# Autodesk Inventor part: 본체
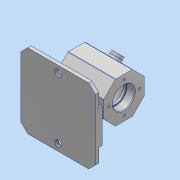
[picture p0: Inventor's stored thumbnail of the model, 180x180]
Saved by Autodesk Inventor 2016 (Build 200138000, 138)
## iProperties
Created: 2018-06
Part Number: 본체
Material: 알루미늄 6061
Document SubType Name: Modeling
Designer: 602-10
Density: 2.7 g/cm^3
Appearance: 알루미늄 - 평지
Author: 602-10
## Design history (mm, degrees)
sketch "스케치1"
  geometry: L1 (55, -55)-(-55, -55); L2 (-55, -55)-(-55, 55); L3 (-55, 55)-(55, 55); L4 (55, 55)-(55, -55); L5 (55, -55)-(-55, 55); L6 (-55, -55)-(55, 55); 1 further point
  constraints: 12 end point, 2 midpoint, 2 parallel, 1 horizontal, 1 perpendicular
  dimensions: "d0" = 110 distance of L1.end L2.end; "d1" = 110 distance of L1.start L1.end
extrude "돌출1" new body sketch "스케치1" distance "d2" = 5; taper "d3" = 0 deg
chamfer "모따기1" distance "d4" = 10; stored, may be unused: second distance "d5" = 2, angle "d6" = 45 deg
sketch "스케치3"
  geometry: L1 (55, -45)-(55, 45) reference; L2 (-55, 25)-(55, 25); L3 (55, 25)-(55, -25); L4 (55, -25)-(-55, -25); L5 (-55, -25)-(-55, 25); L6 (-55, 25)-(55, -25); L7 (55, 25)-(-55, -25); L8 (45, 55)-(-45, 55) reference; 1 further point
  constraints: 12 end point, 2 midpoint, 2 parallel, 1 horizontal, 1 perpendicular, 1 point on line
  dimensions: "d11" = 30 distance between parallel lines of L8 L2
extrude "돌출3" join sketch "스케치3" distance "d12" = 5; taper "d13" = 0 deg
sketch "스케치4"
  geometry: L1 (-55, 45)-(-55, 25) reference; L2 (45, 55)-(-45, 55) reference; L3 (-45, -55)-(45, -55) reference; C1 r 5 at (0, 45); C2 r 5 at (0, -45); 1 further point
  constraints: 2 centre point, 1 vertical alignment
  dimensions: "d14" = 10 diameter of C1; "d15" = 55 distance from line of L1 C1.centre; "d16" = 10 distance from line of C1.centre L2; "d17" = 10 distance from line of L3 C2.centre; "d18" = 10 diameter of C2
extrude "돌출4" cut sketch "스케치4" stored distance "d19" = 5; taper "d20" = 0 deg
sketch "스케치5"
  geometry: L1 (0, 45)-(0, -45) reference; L2 (10, -25)-(10, 25) reference; L3 (32, 12.426)-(49.574, 30); L4 (49.574, 30)-(74.426, 30); L5 (74.426, 30)-(92, 12.426); L6 (92, 12.426)-(92, -12.426); L7 (92, -12.426)-(74.426, -30); L8 (74.426, -30)-(49.574, -30); L9 (49.574, -30)-(32, -12.426); L10 (32, -12.426)-(32, 12.426); 5 further points
  constraints: 16 end point, 3 midpoint, 1 horizontal alignment, 1 vertical, 17 other
  dimensions: "d24" = 62 distance from line of L1 point (62, 0); "d25" = 92 distance between parallel lines of L1 L6
extrude "돌출5" join sketch "스케치5" stored distance "d27" = 70; taper "d28" = 0 deg
sketch "스케치6"
  geometry: L1 (19, 0)-(-19, 0); L2 (19, 5)-(-19, 5); L3 (-19, -5)-(19, -5); A1 r 5 centre (19, 0) between (19, -5) and (19, 5); A2 r 5 centre (-19, 0) between (-19, 5) and (-19, -5); 1 further point
  constraints: 8 end point, 4 point on circle, 4 tangent, 2 centre point, 1 horizontal, 1 midpoint, 1 parallel
  dimensions: "d29" = 5 radius of A1; "d30" = 38 distance of L1.end L1.start
extrude "돌출6" join sketch "스케치6" stored distance "d31" = 70; taper "d32" = 0 deg
fillet "모깎기1" dims "d33" = 2
sketch "스케치7"
  geometry: L1 (70, 24.853)-(70, 0) reference; C1 r 8 at (35, 12.426); 2 further points
  constraints: 1 centre point, 1 horizontal alignment, 1 midpoint, 1 vertical alignment
  dimensions: "d34" = 16 diameter of C1
extrude "돌출7" join sketch "스케치7" distance "d35" = 7; taper "d36" = 0 deg
fillet "모깎기2" dims "d37" = 3
sketch "스케치8"
  geometry: L1 (45, 0)-(-45, 0) reference; C1 r 16 at (0, 62); 2 further points
  constraints: 1 centre point, 1 midpoint, 1 vertical alignment
  dimensions: "d38" = 32 diameter of C1; "d39" = 62 distance from line of L1 C1.centre
extrude "돌출8" cut sketch "스케치8" distance "d40" = 12; taper "d41" = 0 deg
sketch "스케치9"
  geometry: L1 (45, -62)-(-45, -62) reference; C1 r 14 at (0, 0); 2 further points
  constraints: 1 centre point, 1 midpoint, 1 vertical alignment
  dimensions: "d42" = 28 diameter of C1; "d43" = 62 distance from line of L1 C1.centre
extrude "돌출9" cut sketch "스케치9" distance "d44" = 3; taper "d45" = 0 deg
sketch "스케치10"
  geometry: L1 (-45, -62)-(45, -62) reference; C1 r 25 at (0, 0); 1 further point
  constraints: 1 centre point, 1 vertical alignment
  dimensions: "d46" = 50 diameter of C1; "d47" = 62 distance from line of L1 C1.centre
extrude "돌출10" cut sketch "스케치10" distance "d48" = 40; taper "d49" = 0 deg
sketch "스케치11"
  geometry: L1 (45, 0)-(-45, 0) reference; C1 r 16 at (0, 62); 2 further points
  constraints: 1 centre point, 1 midpoint, 1 vertical alignment
  dimensions: "d50" = 32 diameter of C1; "d51" = 62 distance from line of L1 C1.centre
extrude "돌출11" cut sketch "스케치11" distance "d52" = 12; taper "d53" = 0 deg
sketch "스케치12"
  geometry: L1 (45, -62)-(-45, -62) reference; C1 r 14 at (0, 0); 2 further points
  constraints: 1 centre point, 1 midpoint, 1 vertical alignment
  dimensions: "d54" = 28 diameter of C1; "d55" = 62 distance from line of L1 C1.centre
extrude "돌출12" cut sketch "스케치12" distance "d56" = 3; taper "d57" = 0 deg
node "작업 평면1"
sketch "스케치13"
  geometry: L1 (0, 24.853)-(0, 42.426) reference; L2 (70, 42.426)-(0, 42.426) reference; 2 further points
  constraints: 1 other
  dimensions: "d59" = 35 distance from line of L1 point (35, 12.426); "d60" = 30 distance from line of L2 point (35, 12.426)
feature "엠보싱1" sketch "스케치13" dims "d0" = 110, "d1" = 110, "d61" = 0.5, "d62" = 0
sketch "스케치14"
  geometry: L1 (35, 12.426)-(35, -12.426) reference; C1 r 4 at (0, 0); 2 further points
  constraints: 1 centre point, 1 horizontal alignment, 1 midpoint, 1 vertical alignment
  dimensions: "d63" = 8 diameter of C1
extrude "돌출13" cut sketch "스케치14" distance "d64" = 30; taper "d65" = 0 deg
chamfer "모따기2" distance "d66" = 1; stored, may be unused: second distance "d67" = 2, angle "d68" = 45 deg
fillet "모깎기3" dims "d69" = 0.3
fillet "모깎기4" dims "d70" = 3
sketch "스케치15" dims "d71" = 46
  geometry: C1 r 14 at (0, 62) reference; 3 further points
  constraints: 2 vertical alignment, 3 other
hole "구멍1" sketch "스케치15" at (0, 85) diameter "d72" = 3.459; stored, may be unused: countersink angle "d76" = 90 deg, drill point angle "d78" = 118 deg; dims "d73" = 8, "d74" = 4, "d75" = 2, "d77" = 10
fillet "모깎기5" dims "d82" = 1
node "솔리드1"
pattern_circular "원형 패턴1" dims angle "d80" = 360 deg
mirror "대칭1"
other parameters: "d58" = 27
